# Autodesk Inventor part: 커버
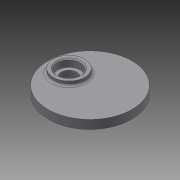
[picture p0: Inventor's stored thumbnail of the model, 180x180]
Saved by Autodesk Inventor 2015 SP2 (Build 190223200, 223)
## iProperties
Created: 2015-06
Part Number: 커버
Material: 일반
Document SubType Name: Modeling
Designer: AMC
Density: 1 g/cm^3
Appearance: 기본값
Author: AMC
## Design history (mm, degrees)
sketch "스케치1"
  geometry: C1 r 40 at (0, 0); 1 further point
  constraints: 1 centre point, 1 coincident
  dimensions: "d0" = 80 diameter of C1
extrude "돌출1" new body sketch "스케치1" distance "d1" = 9; taper "d2" = 0 deg
sketch "스케치5"
  geometry: C1 r 14 at (-11, 0); C2 r 14 at (20, 0); 1 further point
  constraints: 2 centre point, 2 horizontal alignment
  dimensions: "d23" = 28 diameter of C1; "d24" = 28 diameter of C2; "d25" = 11 distance of point (0, 0) C1.centre; "d26" = 20 distance of point (0, 0) C2.centre
extrude "돌출3" join sketch "스케치5" distance "d27" = 3; taper "d28" = 0 deg
sketch "스케치6"
  geometry: C1 r 14 at (0, 0) reference; C2 r 14 at (31, 0) reference; 2 further points
  constraints: 1 coincident
hole "구멍3" sketch "스케치6" at (0, 0) diameter "d29" = 18; stored, may be unused: countersink angle "d33" = 90 deg, drill point angle "d35" = 0 deg; dims "d30" = 6, "d31" = 22, "d32" = 7, "d34" = 8
sketch "스케치8"
  geometry: C1 r 15 at (-20, 0); 1 further point
  constraints: 1 centre point, 1 horizontal alignment
  dimensions: "d43" = 30 diameter of C1; "d44" = 20 distance of point (0, 0) C1.centre
extrude "돌출4" join sketch "스케치8" distance "d45" = 4; taper "d46" = 0 deg
sketch "스케치9"
  geometry: C1 r 15 at (0, 0) reference; 2 further points
  constraints: 1 coincident
hole "구멍5" sketch "스케치9" at (0, 0) diameter "d47" = 15; stored, may be unused: countersink angle "d51" = 90 deg, drill point angle "d53" = 118 deg; dims "d48" = 6, "d49" = 22, "d50" = 7, "d52" = 8
sketch "스케치10"
  geometry: C1 r 14 at (-31, 0) reference; C2 r 14 at (0, 0) reference; 3 further points
  constraints: 1 coincident, 1 horizontal alignment
hole "구멍6" sketch "스케치10" at (0, 0) diameter "d54" = 15; stored, may be unused: countersink angle "d58" = 90 deg, drill point angle "d60" = 118 deg; dims "d55" = 6, "d56" = 22, "d57" = 7, "d59" = 9
fillet "모깎기1" dims "d61" = 2
fillet "모깎기2" dims "d62" = 2
fillet "모깎기3" dims "d63" = 0.3
chamfer "모따기1" distance "d64" = 1; stored, may be unused: second distance "d65" = 2, angle "d66" = 45 deg
node "솔리드1"
node "절단 모서리 투영3"
node "절단 모서리 투영5"
node "절단 모서리 투영6"
